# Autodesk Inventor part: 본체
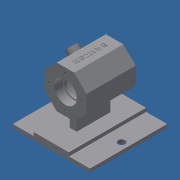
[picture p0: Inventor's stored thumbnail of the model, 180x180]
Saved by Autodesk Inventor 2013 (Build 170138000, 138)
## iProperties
Created: 2018-06
Part Number: 본체
Material: Generic
Document SubType Name: Modeling
Designer: Administrator
Density: 1 g/cm^3
Author: Administrator
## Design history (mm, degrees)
sketch "스케치1"
  geometry: L1 (-12.426, 30)-(12.426, 30); L2 (12.426, 30)-(30, 12.426); L3 (30, 12.426)-(30, -12.426); L4 (30, -12.426)-(12.426, -30); L5 (12.426, -30)-(-12.426, -30); L6 (-12.426, -30)-(-30, -12.426); L7 (-30, -12.426)-(-30, 12.426); L8 (-30, 12.426)-(-12.426, 30); L9 (-12.426, 30)-(0, 0); L10 (0, 0)-(12.426, 30); L11 (-5, -30)-(-5, -52); L12 (-5, -52)-(-25, -52); L13 (-25, -52)-(-25, -57); L14 (-25, -57)-(-55, -57); L15 (-55, -62)-(55, -62); L16 (55, -62)-(55, -57); L17 (55, -57)-(25, -57); L18 (25, -57)-(25, -52); L19 (25, -52)-(5, -52); L20 (5, -52)-(5, -30); L21 (-55, -62)-(-55, -57); L22 (-5, -52)-(5, -52); C1 r 30 at (0, 0); 5 further points
  constraints: 44 end point, 9 parallel, 6 equal length, 4 midpoint, 4 tangent, 4 vertical alignment, 3 horizontal alignment, 3 perpendicular, 2 horizontal, 2 point on line, 2 vertical, 1 centre point, 1 coincident
  dimensions: "d0" = 60 diameter of C1; "d2" = 110 distance of L15.start L15.end; "d4" = 10 distance between parallel lines of L15 L19; "d5" = 5 distance of L15.end L16.end; "d6" = 62 distance from line of L15 point (0, 0); "d7" = 30 distance of L13.end L14.end; "d8" = 10 distance between parallel lines of L20 L11
extrude "돌출1" new body sketch "스케치1" stored distance "d9" = 70; taper "d10" = 0 deg
extrude "돌출2" join sketch "스케치1" stored distance "d11" = 48; taper "d12" = 0 deg
extrude "돌출3" join sketch "스케치1" stored distance "d13" = 110; taper "d14" = 0 deg
sketch "스케치2"
  geometry: L1 (12.426, 35)-(-12.426, 35) reference; L2 (0, 35)-(0, -35); L3 (-12.426, -35)-(12.426, -35) reference; L4 (0, 35)-(16, 35); L5 (30, 35)-(12.426, 35) reference; L6 (16, 35)-(16, 23); L7 (16, 23)-(14, 23); L8 (14, 23)-(14, 20); L9 (14, 20)-(25, 20); L10 (25, 20)-(25, -20); L11 (25, -20)-(14, -20); L12 (14, -20)-(14, -23); L13 (14, -23)-(16, -23); L14 (16, -23)-(16, -35); L15 (12.426, -35)-(30, -35) reference; 1 further point
  constraints: 22 end point, 4 parallel, 3 collinear, 3 vertical alignment, 2 midpoint, 2 perpendicular, 2 point on line, 1 horizontal
  dimensions: "d15" = 12 distance of L4.end L6.end; "d17" = 40 distance of L9.end L10.end; "d18" = 32 diameter of L6 L2; "d19" = 28 diameter of L8 L2; "d20" = 50 diameter of L10 L2
revolve "회전1" sketch "스케치2" stored, may be unused: angle "d21" = 90 deg
sketch "스케치3"
  geometry: C1 r 16 at (0, 0) reference; 1 further point
  constraints: 1 vertical alignment
  dimensions: "d22" = 23 distance of C1.centre point (0, 23)
hole "구멍1" sketch "스케치3" at (0, 23) diameter "d23" = 3.242; stored, may be unused: countersink angle "d27" = 90 deg, drill point angle "d29" = 118 deg; dims "d24" = 8, "d25" = 4, "d26" = 2, "d28" = 10
hole "구멍2" diameter "d35" = 10; stored, may be unused: countersink angle "d39" = 90 deg, drill point angle "d41" = 118 deg; dims "d33" = 55, "d34" = 10, "d36" = 8, "d37" = 4, "d38" = 2, "d40" = 10
fillet "모깎기1" dims "d42" = 3
fillet "모깎기2" dims "d43" = 0.3
node "작업 평면1"
sketch "스케치4"
  geometry: C1 r 8 at (-12.426, 35); 1 further point
  constraints: 1 centre point, 1 coincident
  dimensions: "d45" = 16 diameter of C1
extrude "돌출4" join sketch "스케치4" stored distance "d47" = 110; taper "d48" = 0 deg
hole "구멍3" diameter "d51" = 8; stored, may be unused: countersink angle "d55" = 90 deg, drill point angle "d57" = 118 deg; dims "d49" = 10, "d50" = 10, "d52" = 8, "d53" = 4, "d54" = 2, "d56" = 10
sketch "스케치5"
  geometry: L1 (0, 70)-(24.853, 70) reference; L2 (42.426, 70)-(42.426, 0) reference; 2 further points
  constraints: 1 other
  dimensions: "d58" = 35 distance from line of point (12.426, 35) L1; "d59" = 30 distance from line of point (12.426, 35) L2
feature "엠보싱1" sketch "스케치5" dims "d60" = 0.5, "d61" = 0
node "솔리드1"
pattern_circular "원형 패턴1" dims angle "d31" = 360 deg
mirror "대칭1"
mirror "대칭2"
other parameters: "d44" = 7
